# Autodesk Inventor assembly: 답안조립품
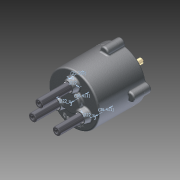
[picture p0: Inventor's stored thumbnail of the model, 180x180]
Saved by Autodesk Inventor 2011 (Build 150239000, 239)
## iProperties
Created: 2015-05
Part Number: 답안조립품
Document SubType Name: Assembly
Designer: Administrator
Author: Administrator
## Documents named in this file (14)
- C:\Documents and Settings\Administrator\바탕 화면\Inventor1급-장정숙\답안조립품.iam
- C:\Documents and Settings\Administrator\바탕 화면\Inventor1급-장정숙\몸체.ipt
- C:\Documents and Settings\Administrator\바탕 화면\Inventor1급-장정숙\베어링 NA 4900.ipt
- C:\Documents and Settings\Administrator\바탕 화면\Inventor1급-장정숙\커버.ipt
- C:\Documents and Settings\Administrator\바탕 화면\Inventor1급-장정숙\오일실.ipt
- C:\Documents and Settings\Administrator\바탕 화면\Inventor1급-장정숙\메인 축.ipt
- C:\Documents and Settings\Administrator\바탕 화면\Inventor1급-장정숙\멈춤링 22 x 1.2.ipt
- C:\Documents and Settings\Administrator\바탕 화면\Inventor1급-장정숙\판캠.ipt
- C:\Documents and Settings\Administrator\바탕 화면\Inventor1급-장정숙\멈춤링 10 x 1.ipt
- C:\Documents and Settings\Administrator\바탕 화면\Inventor1급-장정숙\M5x0.5x20.ipt
- C:\Documents and Settings\Administrator\바탕 화면\Inventor1급-장정숙\슬라이드 축.ipt
- C:\Documents and Settings\Administrator\바탕 화면\Inventor1급-장정숙\가변스프링01.ipt
- C:\Documents and Settings\Administrator\바탕 화면\Inventor1급-장정숙\가변스프링02.ipt
- C:\Documents and Settings\Administrator\바탕 화면\Inventor1급-장정숙\가변스프링03.ipt
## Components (7 placed, 4 different names)
1. M5x0.5x20:1 — 각도:4
2. M5x0.5x20:2 — 각도:2
3. M5x0.5x20:3 — 각도:5
4. M5x0.5x20:4 — 각도:3
5. 가변스프링01:1
6. 가변스프링02:1
7. 가변스프링03:1
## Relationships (4: Angle 4)
- 각도:2 [Angle]: M5x0.5x20:2
- 각도:3 [Angle]: M5x0.5x20:4
- 각도:4 [Angle]: M5x0.5x20:1
- 각도:5 [Angle]: M5x0.5x20:3
